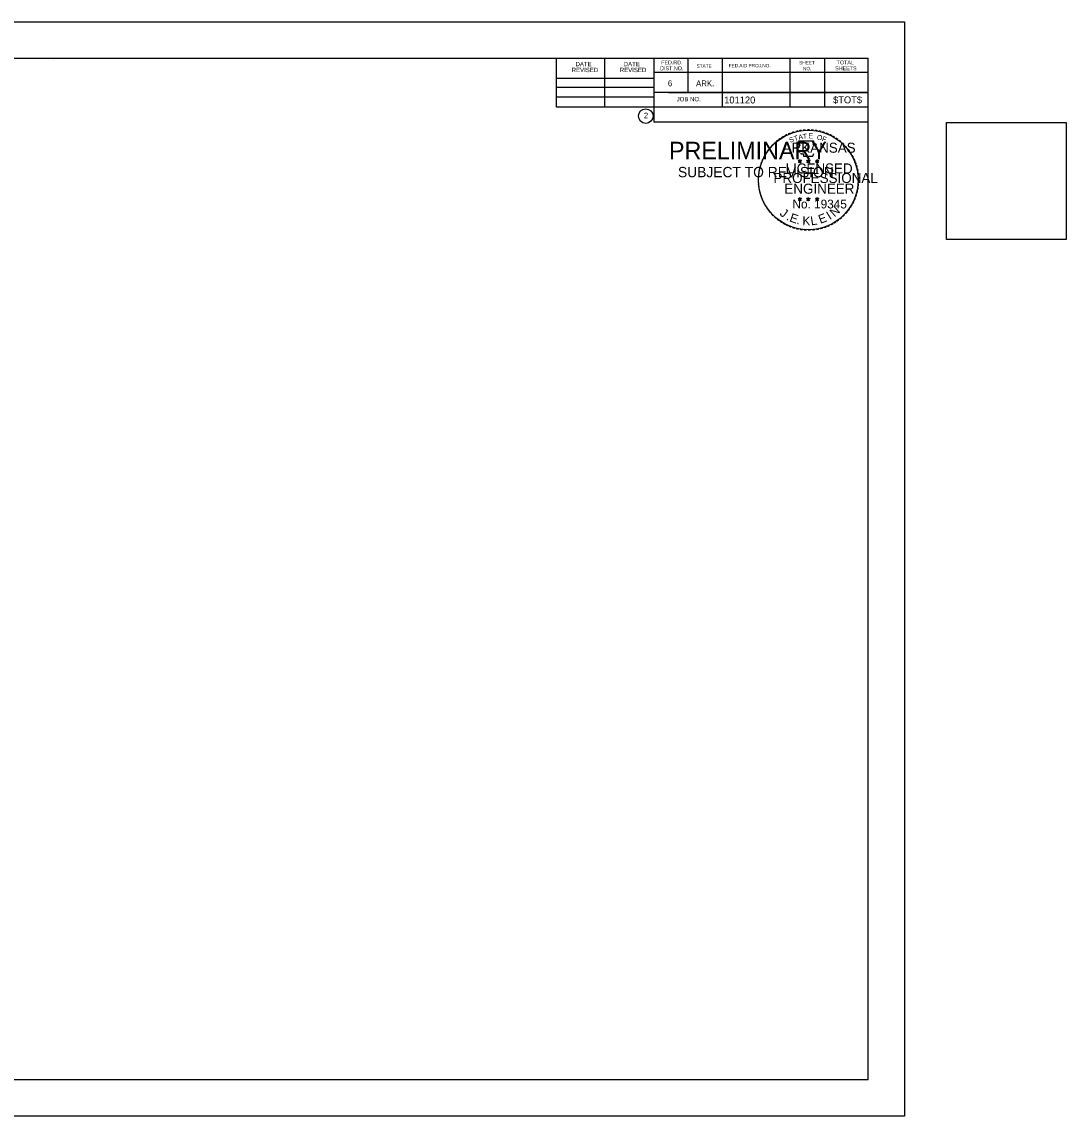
# Model space of a CAD drawing. Extents: x 1334731.2 to 1334773.2, y 402731.5 to 402753.5.
# Drawn here: x 1334752.17 to 1334773.16, y 402731.46 to 402753.46 of the extents above; entities that cross this region are included whole.
import ezdxf

# ---------------------------------------------------------------- set-up
doc = ezdxf.new("R2010")
doc.units = 0
for name, color, linetype in [('Level 63', 7, 'Continuous'), ('R_Border', 7, 'Continuous'), ('R_Border PE', 7, 'Continuous'), ('R_Border Prem', 7, 'Continuous'), ('R_No Plot', 7, 'Continuous')]:
    doc.layers.add(name, color=color, linetype=linetype)

msp = doc.modelspace()

# ---------------------------------------------------------------- linework, layer by layer
at = {"layer": 'Level 63'}
msp.add_lwpolyline([(1334735.91, 402753.46), (1334769.91, 402753.46), (1334769.91, 402731.46), (1334735.91, 402731.46)], close=True, dxfattribs=at)
at = {"layer": 'R_Border'}
for p, q in [((1334737.564, 402752.733), (1334769.182, 402752.733)), ((1334752.816, 402752.707), (1334752.816, 402752.707)), ((1334752.816, 402752.707), (1334752.816, 402752.707)), ((1334762.918, 402751.745), (1334762.918, 402752.733)), ((1334763.886, 402751.745), (1334763.886, 402752.733)), ((1334764.872, 402752.733), (1334764.872, 402751.453)), ((1334765.556, 402752.733), (1334765.556, 402752.039)), ((1334766.25, 402752.733), (1334766.25, 402751.745)), ((1334767.608, 402752.733), (1334767.608, 402751.745)), ((1334768.302, 402752.733), (1334768.302, 402751.745)), ((1334769.182, 402732.187), (1334769.182, 402752.733)), ((1334762.918, 402752.331), (1334764.872, 402752.331)), ((1334769.182, 402752.439), (1334764.872, 402752.439)), ((1334769.182, 402752.441), (1334769.182, 402752.441)), ((1334762.918, 402752.145), (1334764.872, 402752.145)), ((1334769.182, 402752.039), (1334764.872, 402752.039)), ((1334765.168, 402752.039), (1334769.182, 402752.039)), ((1334762.918, 402751.951), (1334764.872, 402751.951)), ((1334769.182, 402751.745), (1334762.918, 402751.745)), ((1334764.872, 402751.453), (1334769.182, 402751.453)), ((1334769.182, 402732.187), (1334737.564, 402732.187))]:
    msp.add_line(p, q, dxfattribs=at)
msp.add_circle((1334764.711, 402751.566), 0.147, dxfattribs=at)
at = {"layer": 'R_Border PE'}
for p, q in [((1334767.774, 402750.67), (1334767.81, 402750.658)), ((1334767.774, 402750.67), (1334767.8, 402750.666)), ((1334767.774, 402750.67), (1334767.798, 402750.657)), ((1334767.788, 402750.628), (1334767.81, 402750.658)), ((1334767.788, 402750.628), (1334767.8, 402750.653)), ((1334767.788, 402750.628), (1334767.808, 402750.65)), ((1334767.81, 402750.696), (1334767.805, 402750.67)), ((1334767.831, 402750.628), (1334767.808, 402750.65)), ((1334767.81, 402750.658), (1334767.81, 402750.696)), ((1334767.81, 402750.696), (1334767.815, 402750.671)), ((1334767.844, 402750.67), (1334767.81, 402750.658)), ((1334767.831, 402750.628), (1334767.81, 402750.658)), ((1334767.844, 402750.67), (1334767.816, 402750.665)), ((1334767.831, 402750.628), (1334767.817, 402750.657)), ((1334767.844, 402750.67), (1334767.824, 402750.659)), ((1334767.943, 402750.67), (1334767.979, 402750.658)), ((1334767.943, 402750.67), (1334767.968, 402750.666)), ((1334767.943, 402750.67), (1334767.966, 402750.657)), ((1334767.956, 402750.628), (1334767.979, 402750.658)), ((1334767.956, 402750.628), (1334767.969, 402750.653)), ((1334767.956, 402750.628), (1334767.977, 402750.65)), ((1334767.979, 402750.696), (1334767.974, 402750.67)), ((1334767.999, 402750.628), (1334767.977, 402750.65)), ((1334767.979, 402750.658), (1334767.979, 402750.696)), ((1334767.979, 402750.696), (1334767.983, 402750.671)), ((1334768.013, 402750.67), (1334767.979, 402750.658)), ((1334767.999, 402750.628), (1334767.979, 402750.658)), ((1334768.013, 402750.67), (1334767.984, 402750.665)), ((1334767.999, 402750.628), (1334767.985, 402750.657)), ((1334768.013, 402750.67), (1334767.992, 402750.659)), ((1334768.121, 402750.669), (1334768.156, 402750.657)), ((1334768.121, 402750.669), (1334768.145, 402750.663)), ((1334768.121, 402750.669), (1334768.144, 402750.656)), ((1334768.133, 402750.627), (1334768.156, 402750.657)), ((1334768.133, 402750.627), (1334768.146, 402750.652)), ((1334768.133, 402750.627), (1334768.156, 402750.649)), ((1334768.156, 402750.694), (1334768.152, 402750.669)), ((1334768.156, 402750.657), (1334768.156, 402750.694)), ((1334768.156, 402750.694), (1334768.16, 402750.669)), ((1334768.191, 402750.669), (1334768.156, 402750.657)), ((1334768.177, 402750.627), (1334768.156, 402750.657)), ((1334768.177, 402750.627), (1334768.156, 402750.649)), ((1334768.191, 402750.669), (1334768.161, 402750.663)), ((1334768.177, 402750.627), (1334768.163, 402750.656)), ((1334768.191, 402750.669), (1334768.169, 402750.658)), ((1334767.773, 402749.907), (1334767.808, 402749.895)), ((1334767.773, 402749.907), (1334767.8, 402749.901)), ((1334767.773, 402749.907), (1334767.798, 402749.894)), ((1334767.788, 402749.865), (1334767.808, 402749.895)), ((1334767.788, 402749.865), (1334767.8, 402749.89)), ((1334767.788, 402749.865), (1334767.808, 402749.888)), ((1334767.808, 402749.931), (1334767.804, 402749.907)), ((1334767.808, 402749.895), (1334767.808, 402749.931)), ((1334767.808, 402749.931), (1334767.814, 402749.907)), ((1334767.844, 402749.907), (1334767.808, 402749.895)), ((1334767.831, 402749.865), (1334767.808, 402749.895)), ((1334767.831, 402749.865), (1334767.808, 402749.887)), ((1334767.844, 402749.907), (1334767.815, 402749.901)), ((1334767.831, 402749.865), (1334767.817, 402749.894)), ((1334767.844, 402749.907), (1334767.824, 402749.896)), ((1334767.942, 402749.907), (1334767.977, 402749.895)), ((1334767.942, 402749.907), (1334767.968, 402749.901)), ((1334767.942, 402749.907), (1334767.966, 402749.894)), ((1334767.956, 402749.865), (1334767.977, 402749.895)), ((1334767.956, 402749.865), (1334767.968, 402749.89)), ((1334767.956, 402749.865), (1334767.977, 402749.888)), ((1334767.977, 402749.931), (1334767.973, 402749.907)), ((1334767.977, 402749.895), (1334767.977, 402749.931)), ((1334767.977, 402749.931), (1334767.982, 402749.907)), ((1334768.013, 402749.907), (1334767.977, 402749.895)), ((1334767.998, 402749.865), (1334767.977, 402749.895)), ((1334767.998, 402749.865), (1334767.977, 402749.887)), ((1334768.013, 402749.907), (1334767.983, 402749.901)), ((1334767.998, 402749.865), (1334767.985, 402749.894)), ((1334768.013, 402749.907), (1334767.991, 402749.896)), ((1334768.121, 402749.906), (1334768.156, 402749.894)), ((1334768.121, 402749.906), (1334768.145, 402749.9)), ((1334768.121, 402749.906), (1334768.144, 402749.893)), ((1334768.133, 402749.864), (1334768.156, 402749.894)), ((1334768.133, 402749.864), (1334768.146, 402749.889)), ((1334768.133, 402749.864), (1334768.156, 402749.887)), ((1334768.156, 402749.93), (1334768.152, 402749.906)), ((1334768.156, 402749.894), (1334768.156, 402749.93)), ((1334768.156, 402749.93), (1334768.16, 402749.906)), ((1334768.191, 402749.906), (1334768.156, 402749.894)), ((1334768.177, 402749.864), (1334768.156, 402749.894)), ((1334768.177, 402749.864), (1334768.156, 402749.886)), ((1334768.191, 402749.906), (1334768.161, 402749.9)), ((1334768.177, 402749.864), (1334768.162, 402749.893)), ((1334768.191, 402749.906), (1334768.169, 402749.895))]:
    msp.add_line(p, q, dxfattribs=at)
for points in [[(1334767.778, 402751.061), (1334767.805, 402750.977)], [(1334768.132, 402750.968), (1334768.146, 402750.996), (1334768.078, 402750.994), (1334768.092, 402751.061), (1334767.778, 402751.061)], [(1334767.828, 402750.817), (1334767.828, 402750.808), (1334767.884, 402750.806), (1334767.879, 402750.758), (1334768.068, 402750.758), (1334768.088, 402750.812)], [(1334767.81, 402750.696), (1334767.831, 402750.628), (1334767.774, 402750.67), (1334767.844, 402750.67), (1334767.788, 402750.628), (1334767.81, 402750.696)], [(1334767.979, 402750.696), (1334767.999, 402750.628), (1334767.943, 402750.67), (1334768.013, 402750.67), (1334767.956, 402750.628), (1334767.979, 402750.696)], [(1334768.156, 402750.694), (1334768.177, 402750.627), (1334768.121, 402750.669), (1334768.191, 402750.669), (1334768.133, 402750.627), (1334768.156, 402750.694)], [(1334767.808, 402749.931), (1334767.831, 402749.865), (1334767.773, 402749.907), (1334767.844, 402749.907), (1334767.788, 402749.865), (1334767.808, 402749.931)], [(1334767.977, 402749.931), (1334767.998, 402749.865), (1334767.942, 402749.907), (1334768.013, 402749.907), (1334767.956, 402749.865), (1334767.977, 402749.931)], [(1334768.156, 402749.93), (1334768.177, 402749.864), (1334768.121, 402749.906), (1334768.191, 402749.906), (1334768.133, 402749.864), (1334768.156, 402749.93)]]:
    msp.add_lwpolyline(points, dxfattribs=at)
for centre, radius in [((1334767.98, 402750.281), 1), ((1334767.809, 402750.658), 0.0174), ((1334767.809, 402750.658), 0.0146), ((1334767.809, 402750.658), 0.0117), ((1334767.809, 402750.658), 0.00999), ((1334767.809, 402750.658), 0.00753), ((1334767.809, 402750.658), 0.00499), ((1334767.809, 402750.658), 0.00299), ((1334767.977, 402750.658), 0.0174), ((1334767.977, 402750.658), 0.0146), ((1334767.977, 402750.658), 0.0117), ((1334767.977, 402750.658), 0.00999), ((1334767.977, 402750.658), 0.00753), ((1334767.977, 402750.658), 0.00499), ((1334767.977, 402750.658), 0.00299), ((1334768.155, 402750.657), 0.0174), ((1334768.155, 402750.657), 0.0146), ((1334768.155, 402750.657), 0.0117), ((1334768.155, 402750.657), 0.00999), ((1334768.155, 402750.657), 0.00753), ((1334768.155, 402750.657), 0.00499), ((1334768.155, 402750.657), 0.00299), ((1334767.808, 402749.895), 0.0174), ((1334767.808, 402749.895), 0.0146), ((1334767.808, 402749.895), 0.0117), ((1334767.808, 402749.895), 0.00999), ((1334767.808, 402749.895), 0.00753), ((1334767.808, 402749.895), 0.00499), ((1334767.808, 402749.895), 0.00299), ((1334767.976, 402749.895), 0.0174), ((1334767.976, 402749.895), 0.0146), ((1334767.976, 402749.895), 0.0117), ((1334767.976, 402749.895), 0.00999), ((1334767.976, 402749.895), 0.00753), ((1334767.976, 402749.895), 0.00499), ((1334767.976, 402749.895), 0.00299), ((1334768.154, 402749.894), 0.0174), ((1334768.154, 402749.894), 0.0146), ((1334768.154, 402749.894), 0.0117), ((1334768.154, 402749.894), 0.00999), ((1334768.154, 402749.894), 0.00753), ((1334768.154, 402749.894), 0.00499), ((1334768.154, 402749.894), 0.00299)]:
    msp.add_circle(centre, radius, dxfattribs=at)
at = {"layer": 'R_No Plot'}
msp.add_lwpolyline([(1334770.755, 402751.435), (1334773.16, 402751.435), (1334773.16, 402749.085), (1334770.755, 402749.085)], close=True, dxfattribs=at)

# ---------------------------------------------------------------- texts
at = {"layer": 'R_Border'}
for s, height, p in [('FED.RD.', 0.0782, (1334765.02, 402752.605)), ('TOTAL', 0.0782, (1334768.546, 402752.605)), ('REVISED', 0.0879, (1334763.222, 402752.449)), ('DATE', 0.0879, (1334763.3, 402752.567)), ('REVISED', 0.0879, (1334764.19, 402752.449)), ('DATE', 0.0879, (1334764.268, 402752.567)), ('DIST.NO.', 0.0782, (1334765, 402752.487)), ('STATE', 0.0684, (1334765.732, 402752.537)), ('FED.AID PROJ.NO.', 0.0684, (1334766.378, 402752.547)), ('SHEET', 0.0684, (1334767.794, 402752.605)), ('NO.', 0.0684, (1334767.872, 402752.487)), ('SHEETS', 0.0782, (1334768.518, 402752.487)), ('6', 0.117, (1334765.156, 402752.165)), ('ARK.', 0.1172, (1334765.722, 402752.165)), ('JOB NO.', 0.0879, (1334765.332, 402751.863)), ('101120', 0.14, (1334766.288, 402751.819)), ('$TOT$', 0.14, (1334768.476, 402751.822)), ('2', 0.117, (1334764.673, 402751.518))]:
    msp.add_text(s, height=height, rotation=360, dxfattribs=at).set_placement(p)
at = {"layer": 'R_Border PE'}
for s, height, rotation, p in [('-', 0.161, 34.0636, (1334767.464, 402751.078)), ('-', 0.161, 28.7918, (1334767.524, 402751.116)), ('-', 0.161, 24.3072, (1334767.588, 402751.148)), ('S', 0.101, 21.594, (1334767.613, 402751.028)), ('-', 0.161, 19.1761, (1334767.653, 402751.175)), ('T', 0.101, 16.4036, (1334767.705, 402751.062)), ('-', 0.161, 13.6301, (1334767.729, 402751.198)), ('A', 0.101, 11.2132, (1334767.788, 402751.087)), ('-', 0.161, 10.2193, (1334767.796, 402751.215)), ('T', 0.101, 6.0228, (1334767.873, 402751.104)), ('-', 0.161, 5.8968, (1334767.87, 402751.225)), ('-', 0.161, 0.1862, (1334767.947, 402751.233)), ('E', 0.101, 0.8323, (1334767.985, 402751.116)), ('-', 0.161, 357.743, (1334768.02, 402751.232)), ('-', 0.161, 352.1617, (1334768.095, 402751.225)), ('O', 0.101, 350.4515, (1334768.146, 402751.094)), ('-', 0.161, 347.2049, (1334768.167, 402751.215)), ('F', 0.101, 340.0707, (1334768.243, 402751.071)), ('-', 0.161, 342.3362, (1334768.233, 402751.198)), ('-', 0.161, 337.8551, (1334768.305, 402751.177)), ('-', 0.161, 334.1211, (1334768.369, 402751.15)), ('-', 0.161, 329.6409, (1334768.427, 402751.121)), ('-', 0.161, 50.6142, (1334767.228, 402750.862)), ('-', 0.161, 48.4231, (1334767.269, 402750.909)), ('-', 0.161, 42.9622, (1334767.315, 402750.958)), ('-', 0.161, 38.9507, (1334767.358, 402751)), ('-', 0.161, 36.2317, (1334767.405, 402751.039)), ('-', 0.161, 325.8627, (1334768.492, 402751.084)), ('-', 0.161, 320.5297, (1334768.554, 402751.042)), ('-', 0.161, 315.5786, (1334768.614, 402750.992)), ('-', 0.161, 309.8797, (1334768.671, 402750.936)), ('-', 0.161, 67.7743, (1334767.096, 402750.627)), ('-', 0.161, 62.8713, (1334767.122, 402750.688)), ('-', 0.161, 58.0706, (1334767.154, 402750.751)), ('-', 0.161, 54.2325, (1334767.187, 402750.803)), ('-', 0.161, 306.6522, (1334768.725, 402750.876)), ('-', 0.141, 303.6753, (1334768.773, 402750.819)), ('-', 0.161, 299.6684, (1334768.806, 402750.757)), ('-', 0.161, 294.6628, (1334768.839, 402750.696)), ('-', 0.161, 81.2013, (1334767.042, 402750.42)), ('-', 0.161, 75.461, (1334767.055, 402750.491)), ('-', 0.161, 72.3945, (1334767.075, 402750.564)), ('-', 0.161, 290.5728, (1334768.864, 402750.639)), ('-', 0.161, 285.1233, (1334768.888, 402750.58)), ('-', 0.161, 280.5493, (1334768.909, 402750.504)), ('-', 0.161, 94.1959, (1334767.035, 402750.206)), ('-', 0.161, 89.0622, (1334767.032, 402750.28)), ('-', 0.161, 85.1863, (1334767.034, 402750.35)), ('-', 0.161, 276.5962, (1334768.924, 402750.428)), ('-', 0.161, 274.3301, (1334768.93, 402750.355)), ('-', 0.161, 269.9407, (1334768.933, 402750.29)), ('-', 0.161, 98.9479, (1334767.042, 402750.14)), ('-', 0.161, 101.7149, (1334767.056, 402750.065)), ('-', 0.161, 105.4578, (1334767.072, 402750.005)), ('-', 0.161, 255.7626, (1334768.914, 402750.089)), ('-', 0.161, 260.9953, (1334768.924, 402750.158)), ('-', 0.161, 263.5172, (1334768.931, 402750.224)), ('-', 0.161, 109.0874, (1334767.093, 402749.942)), ('-', 0.161, 114.0643, (1334767.119, 402749.882)), ('-', 0.161, 115.7289, (1334767.15, 402749.82)), ('-', 0.161, 244.6197, (1334768.846, 402749.886)), ('-', 0.161, 247.8887, (1334768.873, 402749.949)), ('-', 0.161, 252.8681, (1334768.895, 402750.017)), ('-', 0.161, 120.4471, (1334767.186, 402749.76)), ('-', 0.161, 125.8934, (1334767.226, 402749.704)), ('-', 0.161, 130.7181, (1334767.273, 402749.647)), ('-', 0.161, 134.2238, (1334767.325, 402749.593)), ('J', 0.177, 323.9056, (1334767.391, 402749.582)), ('E', 0.177, 340.8881, (1334767.588, 402749.452)), ('E', 0.177, 20.5042, (1334768.22, 402749.398)), ('I', 0.177, 32.2382, (1334768.409, 402749.474)), ('N', 0.177, 42.9205, (1334768.507, 402749.527)), ('-', 0.161, 231.2538, (1334768.723, 402749.687)), ('-', 0.161, 233.8452, (1334768.767, 402749.745)), ('-', 0.161, 239.0712, (1334768.807, 402749.81)), ('-', 0.161, 138.9338, (1334767.378, 402749.547)), ('-', 0.161, 144.6463, (1334767.434, 402749.505)), ('-', 0.161, 148.0898, (1334767.49, 402749.468)), ('-', 0.161, 151.5704, (1334767.548, 402749.435)), ('-', 0.161, 154.6002, (1334767.602, 402749.411)), ('.', 0.177, 336.3407, (1334767.524, 402749.486)), ('.', 0.177, 350.694, (1334767.735, 402749.398)), ('K', 0.177, 359.3149, (1334767.86, 402749.371)), ('L', 0.177, 8.7702, (1334768.036, 402749.367)), ('-', 0.161, 207.3568, (1334768.457, 402749.458)), ('-', 0.161, 212.2491, (1334768.514, 402749.493)), ('-', 0.161, 215.7363, (1334768.566, 402749.532)), ('-', 0.161, 221.0851, (1334768.622, 402749.579)), ('-', 0.161, 225.7653, (1334768.674, 402749.631)), ('-', 0.161, 158.5612, (1334767.664, 402749.385)), ('-', 0.161, 162.7983, (1334767.734, 402749.363)), ('-', 0.161, 167.5555, (1334767.805, 402749.348)), ('-', 0.161, 173.1155, (1334767.883, 402749.336)), ('-', 0.161, 176.5183, (1334767.959, 402749.33)), ('-', 0.161, 181.5918, (1334768.035, 402749.332)), ('-', 0.161, 185.8167, (1334768.115, 402749.34)), ('-', 0.161, 191.2858, (1334768.19, 402749.353)), ('-', 0.161, 195.4743, (1334768.264, 402749.374)), ('-', 0.161, 200.7184, (1334768.332, 402749.398)), ('-', 0.161, 204.2516, (1334768.394, 402749.424))]:
    msp.add_text(s, height=height, rotation=rotation, dxfattribs=at).set_placement(p)
for s, height, p in [('ARKANSAS', 0.2016, (1334767.461, 402750.829)), ('LICENSED', 0.2016, (1334767.521, 402750.412)), ('PROFESSIONAL', 0.20156, (1334767.278, 402750.22)), ('ENGINEER', 0.2016, (1334767.497, 402750.005)), ('No. 19345', 0.1771, (1334767.66, 402749.709))]:
    msp.add_text(s, height=height, dxfattribs=at).set_placement(p)
at = {"layer": 'R_Border Prem'}
for s, height, p in [('PRELIMINARY', 0.35, (1334765.178, 402750.699)), ('DWB', 0.002, (1334765.252, 402750.884)), ('SUBJECT TO REVISION', 0.20751, (1334765.359, 402750.336))]:
    msp.add_text(s, height=height, rotation=360, dxfattribs=at).set_placement(p)

doc.saveas('drawing.dxf')
